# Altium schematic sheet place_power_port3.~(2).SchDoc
size A4
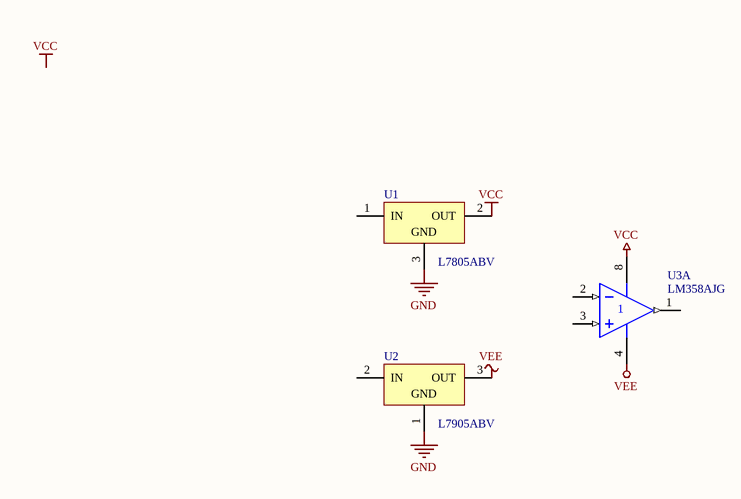
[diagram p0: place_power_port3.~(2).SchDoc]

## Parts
U1  L7805ABV  [TO220ABN]
U2  L7905ABV  [TO220V]
U3  LM358AJG  [JG008]  (part A of 2)

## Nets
GND: U1.3(GND) U2.1(GND)
VCC: U1.2(OUT) U3.8(V+)
VEE: U2.3(OUT) U3.4(V-)

Not connected (* = marked no-connect by the designer): U1 1(IN); U2 2(IN); U3 1(OUT) 2(IN-) 3(IN+)

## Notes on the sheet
- Labels drawn without touching a wire or pin: VCC

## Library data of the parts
U1 = L7805ABV: Precision 1A Regulator; Note: Tab is connected to pin 3 (GND).
U2 = L7905ABV: ?2%Negative Voltage Regulator; Note: Tab is connected to pin 3 (IN).
U3 = LM358AJG: Dual Operational Amplifier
